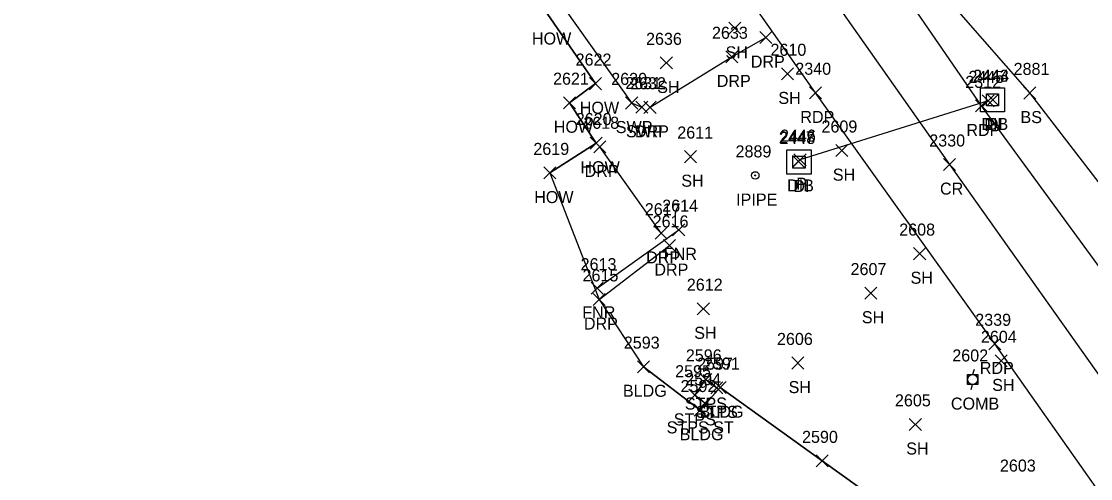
# Model space of a CAD drawing. Extents: x 1638344 to 1639591, y 610835 to 612202.
# Drawn here: x 1638879.7 to 1639057.3, y 611382.3 to 611458.3 of the extents above; entities that cross this region are included whole.
import ezdxf

# ---------------------------------------------------------------- set-up
doc = ezdxf.new("R2010")
doc.units = 0
for name, color, linetype in [('D_A', 7, 'Continuous'), ('D_I', 7, 'Continuous'), ('D_TIC', 7, 'Continuous'), ('DCP', 7, 'Continuous'), ('DS', 7, 'Continuous'), ('L_A', 7, 'Continuous'), ('L_I', 7, 'Continuous'), ('L_TIC', 7, 'Continuous'), ('LBC', 7, 'Continuous'), ('LBF', 7, 'Continuous'), ('LELB', 7, 'Continuous'), ('LFNC', 7, 'Continuous'), ('LSOGP', 7, 'Continuous'), ('M_A', 7, 'Continuous'), ('M_I', 7, 'Continuous'), ('MPIP', 7, 'Continuous'), ('P_A', 7, 'Continuous'), ('P_I', 7, 'Continuous'), ('P_TIC', 7, 'Continuous'), ('PET', 7, 'Continuous'), ('PRC', 7, 'Continuous'), ('R_A', 7, 'Continuous'), ('R_I', 7, 'Continuous'), ('R_TIC', 7, 'Continuous'), ('RDP', 7, 'Continuous'), ('RSW', 7, 'Continuous'), ('U_A', 7, 'Continuous'), ('U_I', 7, 'Continuous'), ('UP', 7, 'Continuous')]:
    doc.layers.add(name, color=color, linetype=linetype)

msp = doc.modelspace()

# ---------------------------------------------------------------- linework, layer by layer
at = {"layer": 'D_TIC'}
for points in [[(1639039.24, 611444.05), (1639041.24, 611446.05)], [(1639041.24, 611444.05), (1639039.24, 611446.05)], [(1639040.03, 611444.23), (1639042.03, 611446.23)], [(1639042.03, 611444.23), (1639040.03, 611446.23)], [(1639007.76, 611434.01), (1639009.76, 611436.01)], [(1639009.76, 611434.01), (1639007.76, 611436.01)], [(1639008.01, 611434.29), (1639010.01, 611436.29)], [(1639010.01, 611434.29), (1639008.01, 611436.29)]]:
    msp.add_lwpolyline(points, dxfattribs=at)
at = {"layer": 'DCP'}
msp.add_lwpolyline([(1639040.24, 611445.05), (1639009.01, 611435.29)], dxfattribs=at)
at = {"layer": 'DS'}
for p, q in [((1639038.97, 611447.24), (1639042.97, 611447.24)), ((1639038.97, 611443.24), (1639038.97, 611447.24)), ((1639039.97, 611444.24), (1639039.97, 611446.24)), ((1639039.97, 611446.24), (1639041.97, 611446.24)), ((1639041.97, 611446.24), (1639041.97, 611444.24)), ((1639042.97, 611447.24), (1639042.97, 611443.24)), ((1639041.97, 611444.24), (1639039.97, 611444.24)), ((1639040.98, 611445.24), (1639040.98, 611445.24)), ((1639040.98, 611445.24), (1639040.98, 611445.24)), ((1639042.97, 611443.24), (1639038.97, 611443.24)), ((1639006.85, 611436.9), (1639010.85, 611436.9)), ((1639006.85, 611432.9), (1639006.85, 611436.9)), ((1639010.85, 611436.9), (1639010.85, 611432.9)), ((1639007.85, 611433.9), (1639007.85, 611435.9)), ((1639007.85, 611435.9), (1639009.85, 611435.9)), ((1639009.85, 611435.9), (1639009.85, 611433.9)), ((1639009.85, 611433.9), (1639007.85, 611433.9)), ((1639008.85, 611434.91), (1639008.85, 611434.91)), ((1639008.85, 611434.91), (1639008.85, 611434.91)), ((1639010.85, 611432.9), (1639006.85, 611432.9))]:
    msp.add_line(p, q, dxfattribs=at)
at = {"layer": 'L_TIC'}
for points in [[(1638997.17, 611456.12), (1638999.17, 611458.12)], [(1638999.17, 611456.12), (1638997.17, 611458.12)], [(1638985.82, 611450.37), (1638987.82, 611452.37)], [(1638987.82, 611450.37), (1638985.82, 611452.37)], [(1639005.93, 611448.54), (1639007.93, 611450.54)], [(1639007.93, 611448.54), (1639005.93, 611450.54)], [(1638974.07, 611446.92), (1638976.07, 611448.92)], [(1638976.07, 611446.92), (1638974.07, 611448.92)], [(1639046.18, 611445.37), (1639048.17, 611447.37)], [(1639048.17, 611445.37), (1639046.18, 611447.37)], [(1638969.75, 611443.75), (1638971.75, 611445.75)], [(1638971.75, 611443.75), (1638969.75, 611445.75)], [(1638974.17, 611437.04), (1638976.17, 611439.04)], [(1638976.17, 611437.04), (1638974.17, 611439.04)], [(1639014.97, 611435.8), (1639016.97, 611437.8)], [(1639016.97, 611435.8), (1639014.97, 611437.8)], [(1638989.81, 611434.79), (1638991.81, 611436.79)], [(1638991.81, 611434.79), (1638989.81, 611436.79)], [(1638966.49, 611432.09), (1638968.49, 611434.09)], [(1638968.49, 611432.09), (1638966.49, 611434.09)], [(1638987.87, 611422.65), (1638989.87, 611424.65)], [(1638989.87, 611422.65), (1638987.87, 611424.65)], [(1639027.88, 611418.68), (1639029.88, 611420.68)], [(1639029.88, 611418.68), (1639027.88, 611420.68)], [(1638974.33, 611412.93), (1638976.33, 611414.93)], [(1638976.33, 611412.93), (1638974.33, 611414.93)], [(1639019.79, 611412.12), (1639021.79, 611414.12)], [(1639021.79, 611412.12), (1639019.79, 611414.12)], [(1638991.96, 611409.53), (1638993.96, 611411.53)], [(1638993.96, 611409.53), (1638991.96, 611411.53)], [(1638982.02, 611399.9), (1638984.02, 611401.9)], [(1638984.02, 611399.9), (1638982.02, 611401.9)], [(1639007.63, 611400.51), (1639009.63, 611402.51)], [(1639009.63, 611400.51), (1639007.63, 611402.51)], [(1639041.43, 611400.87), (1639043.43, 611402.87)], [(1639043.43, 611400.87), (1639041.43, 611402.87)], [(1638992.38, 611397.78), (1638994.38, 611399.78)], [(1638994.38, 611397.78), (1638992.38, 611399.78)], [(1638994.19, 611396.4), (1638996.19, 611398.4)], [(1638996.19, 611396.4), (1638994.19, 611398.4)], [(1638994.76, 611396.43), (1638996.76, 611398.43)], [(1638996.76, 611396.43), (1638994.76, 611398.43)], [(1638990.54, 611395.15), (1638992.54, 611397.15)], [(1638992.54, 611395.15), (1638990.54, 611397.15)], [(1638991.44, 611392.68), (1638993.44, 611394.68)], [(1638993.44, 611392.68), (1638991.44, 611394.68)], [(1638992.22, 611393.82), (1638994.22, 611395.82)], [(1638994.22, 611393.82), (1638992.22, 611395.82)], [(1639027.16, 611390.31), (1639029.16, 611392.31)], [(1639029.16, 611390.31), (1639027.16, 611392.31)], [(1639011.69, 611384.24), (1639013.69, 611386.24)], [(1639013.69, 611384.24), (1639011.69, 611386.24)]]:
    msp.add_lwpolyline(points, dxfattribs=at)
at = {"layer": 'LBC'}
for points in [[(1638967.49, 611433.08), (1638975.17, 611438.04), (1638970.75, 611444.76), (1638975.07, 611447.92), (1638967.12, 611459.42), (1638958.39, 611472.15), (1638953.37, 611468.84), (1638948.31, 611476.61)], [(1639030.18, 611240.11), (1639055.01, 611274.11), (1639074.76, 611301.1), (1639056.76, 611314.92), (1639059.81, 611319.01), (1639041.03, 611332.86), (1639050.69, 611345.89), (1639051.32, 611346.8), (1639056.15, 611353.65), (1639047.23, 611360.01), (1639049.34, 611363.03), (1639049.78, 611363.31), (1639052.48, 611367.11), (1639048.07, 611370.38), (1639042.99, 611363.34), (1639028.13, 611374.16), (1639012.69, 611385.24), (1638995.76, 611397.43), (1638992.44, 611393.68), (1638983.02, 611400.9)]]:
    msp.add_lwpolyline(points, dxfattribs=at)
at = {"layer": 'LBF'}
msp.add_lwpolyline([(1638993.22, 611394.82), (1638991.53, 611396.15), (1638993.38, 611398.78), (1638995.19, 611397.4)], dxfattribs=at)
at = {"layer": 'LELB'}
msp.add_lwpolyline([(1639083.1, 611392.43), (1639064.29, 611424.19), (1639047.18, 611446.37), (1639027.15, 611469.33), (1639020.17, 611481.13), (1639024.02, 611486.6)], dxfattribs=at)
at = {"layer": 'LFNC'}
msp.add_lwpolyline([(1638975.33, 611413.93), (1638988.87, 611423.65)], dxfattribs=at)
at = {"layer": 'LSOGP'}
msp.add_lwpolyline([(1638866.35, 611571.46), (1638891.21, 611537.16), (1638898.26, 611527.19), (1638908.02, 611525.06), (1638919.13, 611516.13), (1638930.92, 611504.47), (1638933.49, 611502.4), (1638935.84, 611500.51), (1638941.41, 611480.46), (1638948.31, 611476.61), (1638953.37, 611468.84), (1638958.39, 611472.15), (1638967.12, 611459.42), (1638975.07, 611447.92), (1638970.75, 611444.76), (1638975.17, 611438.04), (1638967.49, 611433.08), (1638975.65, 611412.07), (1638983.02, 611400.9), (1638992.44, 611393.68), (1638995.76, 611397.43), (1639012.69, 611385.24), (1639028.13, 611374.16)], dxfattribs=at)
at = {"layer": 'MPIP'}
for radius in [0.625, 0.0833]:
    msp.add_circle((1639001.58, 611432.67), radius, dxfattribs=at)
at = {"layer": 'P_TIC'}
for points in [[(1639010.58, 611445.4), (1639012.58, 611447.4)], [(1639012.58, 611445.4), (1639010.58, 611447.4)], [(1639038.15, 611443.22), (1639040.15, 611445.22)], [(1639040.15, 611443.22), (1639038.15, 611445.22)], [(1639032.82, 611433.48), (1639034.82, 611435.48)], [(1639034.82, 611433.48), (1639032.82, 611435.48)], [(1639040.38, 611403.69), (1639042.38, 611405.69)], [(1639042.38, 611403.69), (1639040.38, 611405.69)]]:
    msp.add_lwpolyline(points, dxfattribs=at)
at = {"layer": 'PET'}
for points in [[(1639148.64, 611331.08), (1639142.07, 611329.18), (1639135.7, 611328.74), (1639125.69, 611331.15), (1639119.18, 611334.88), (1639114.19, 611340.57), (1639098.76, 611361.78), (1639080.32, 611387.34), (1639061.62, 611413.48), (1639039.15, 611444.22), (1639014.34, 611480.36), (1638988.41, 611516.9), (1638963.39, 611551.85), (1638935.46, 611588.7), (1638918.51, 611609.36), (1638899.73, 611630.86), (1638874.41, 611653.86), (1638846.55, 611674.47), (1638833.14, 611682.54), (1638823.86, 611689.16)], [(1639117.36, 611283.38), (1639114.12, 611301.89), (1639095.51, 611328.5), (1639070.51, 611363.26), (1639041.38, 611404.69), (1639011.58, 611446.4), (1638984.33, 611485.15), (1638954.17, 611527.5), (1638934.33, 611554.77), (1638918.88, 611575.58), (1638893.27, 611605.67), (1638868.12, 611629.84), (1638836.66, 611652.85), (1638812.43, 611667.64)]]:
    msp.add_lwpolyline(points, dxfattribs=at)
at = {"layer": 'PRC'}
msp.add_lwpolyline([(1638818.79, 611678.84), (1638843.98, 611663.35), (1638876.44, 611637.39), (1638906.24, 611607.19), (1638934.14, 611573.69), (1638965.31, 611531.43), (1638998.82, 611484.34), (1639033.82, 611434.48), (1639068.01, 611386.3), (1639093.94, 611350.49), (1639111.89, 611325.38), (1639129.23, 611302.77)], dxfattribs=at)
at = {"layer": 'R_TIC'}
for points in [[(1639002.36, 611454.59), (1639004.36, 611456.59)], [(1639004.36, 611454.59), (1639002.36, 611456.59)], [(1638996.71, 611451.38), (1638998.71, 611453.38)], [(1638998.71, 611451.38), (1638996.71, 611453.38)], [(1638980.06, 611443.71), (1638982.06, 611445.71)], [(1638982.06, 611443.71), (1638980.06, 611445.71)], [(1638981.76, 611443.01), (1638983.76, 611445.01)], [(1638983.76, 611443.01), (1638981.76, 611445.01)], [(1638983.11, 611442.99), (1638985.11, 611444.99)], [(1638985.11, 611442.99), (1638983.11, 611444.99)], [(1638974.77, 611436.42), (1638976.77, 611438.42)], [(1638976.77, 611436.42), (1638974.77, 611438.42)], [(1638984.98, 611422.06), (1638986.98, 611424.06)], [(1638986.98, 611422.06), (1638984.98, 611424.06)], [(1638986.35, 611420.04), (1638988.34, 611422.04)], [(1638988.34, 611420.04), (1638986.35, 611422.04)], [(1638974.65, 611411.07), (1638976.65, 611413.07)], [(1638976.65, 611411.07), (1638974.65, 611413.07)]]:
    msp.add_lwpolyline(points, dxfattribs=at)
at = {"layer": 'RDP'}
for points in [[(1638984.11, 611443.99), (1638997.71, 611452.38), (1639003.36, 611455.59)], [(1638985.98, 611423.06), (1638975.77, 611437.42)], [(1638975.65, 611412.07), (1638987.34, 611421.04)]]:
    msp.add_lwpolyline(points, dxfattribs=at)
at = {"layer": 'RSW'}
msp.add_lwpolyline([(1638949.07, 611476.91), (1638955.12, 611480.86), (1638963.04, 611470.12), (1638981.06, 611444.71), (1638982.76, 611444.01)], dxfattribs=at)
at = {"layer": 'UP'}
for p, q in [((1639037.93, 611400.43), (1639037.68, 611399.6)), ((1639036.85, 611397.93), (1639036.85, 611399.6)), ((1639036.85, 611399.6), (1639038.52, 611399.6)), ((1639038.52, 611397.93), (1639036.85, 611397.93)), ((1639037.43, 611397.1), (1639037.68, 611397.93)), ((1639037.68, 611398.77), (1639037.68, 611398.77)), ((1639038.52, 611399.6), (1639038.52, 611397.93))]:
    msp.add_line(p, q, dxfattribs=at)
msp.add_circle((1639037.68, 611398.77), 0.833, dxfattribs=at)

# ---------------------------------------------------------------- texts
at = {"layer": 'D_A'}
for s, p in [('DIB', (1639039.13, 611440.23)), ('DI', (1639040.03, 611440.24)), ('P', (1639039.61, 611440.05)), ('DIB', (1639006.87, 611430.01)), ('DI', (1639007.91, 611429.91)), ('P', (1639008.39, 611430.29))]:
    msp.add_text(s, height=2, dxfattribs=at).set_placement(p)
at = {"layer": 'D_I'}
for s, p in [('2445', (1639036.98, 611448.05)), ('2443', (1639037.72, 611448.24)), ('2444', (1639037.77, 611448.23)), ('2447', (1639005.5, 611438.01)), ('2448', (1639005.59, 611437.91)), ('2446', (1639005.7, 611438.29))]:
    msp.add_text(s, height=2, dxfattribs=at).set_placement(p)
at = {"layer": 'L_A'}
for s, p in [('HOW', (1638964.5, 611454.42)), ('SH', (1638996.66, 611452.12)), ('SH', (1638985.31, 611446.37)), ('SH', (1639005.42, 611444.55)), ('HOW', (1638972.45, 611442.92)), ('BS', (1639045.62, 611441.37)), ('HOW', (1638968.14, 611439.76)), ('HOW', (1638972.56, 611433.04)), ('SH', (1639014.46, 611431.8)), ('SH', (1638989.3, 611430.8)), ('HOW', (1638964.88, 611428.08)), ('FNR', (1638986.4, 611418.65)), ('SH', (1639027.37, 611414.68)), ('FNR', (1638972.87, 611408.93)), ('SH', (1639019.28, 611408.12)), ('SH', (1638991.45, 611405.53)), ('BLDG', (1638979.61, 611395.9)), ('SH', (1639007.12, 611396.51)), ('SH', (1639040.92, 611396.87)), ('STPS', (1638989.9, 611393.78)), ('STPS', (1638991.71, 611392.4)), ('BLDG', (1638992.35, 611392.43)), ('STPS', (1638988.05, 611391.15)), ('STPS ST', (1638986.87, 611389.82)), ('BLDG', (1638989.03, 611388.68)), ('SH', (1639026.65, 611386.31))]:
    msp.add_text(s, height=2, dxfattribs=at).set_placement(p)
at = {"layer": 'L_I'}
for s, p in [('2636', (1638983.45, 611454.37)), ('2622', (1638971.76, 611450.92)), ('2610', (1639004.11, 611452.55)), ('2881', (1639044.48, 611449.37)), ('2621', (1638968.01, 611447.75)), ('2620', (1638971.78, 611441.04)), ('2611', (1638988.64, 611438.8)), ('2609', (1639012.58, 611439.8)), ('2619', (1638964.74, 611436.08)), ('2614', (1638986.13, 611426.65)), ('2608', (1639025.49, 611422.68)), ('2613', (1638972.59, 611416.93)), ('2607', (1639017.41, 611416.12)), ('2612', (1638990.22, 611413.53)), ('2604', (1639039.05, 611404.87)), ('2593', (1638979.76, 611403.9)), ('2606', (1639005.19, 611404.51)), ('2596', (1638990.06, 611401.78)), ('2597', (1638991.93, 611400.4)), ('2591', (1638993.07, 611400.43)), ('2595', (1638988.28, 611399.15)), ('2594', (1638989.96, 611397.82)), ('2592', (1638989.18, 611396.68)), ('2605', (1639024.78, 611394.31)), ('2590', (1639009.35, 611388.24)), ('2603', (1639042.21, 611383.47))]:
    msp.add_text(s, height=2, dxfattribs=at).set_placement(p)
at = {"layer": 'M_A'}
msp.add_text('IPIPE', height=2, dxfattribs=at).set_placement((1638998.41, 611427.67))
at = {"layer": 'M_I'}
msp.add_text('2889', height=2, dxfattribs=at).set_placement((1638998.31, 611435.67))
at = {"layer": 'P_A'}
for s, p in [('RDP', (1639009.07, 611441.4)), ('RDP', (1639036.64, 611439.22)), ('CR', (1639032.26, 611429.48)), ('RDP', (1639038.87, 611399.69))]:
    msp.add_text(s, height=2, dxfattribs=at).set_placement(p)
at = {"layer": 'P_I'}
for s, p in [('2340', (1639008.23, 611449.4)), ('2312', (1639036.46, 611447.22)), ('2330', (1639030.48, 611437.48)), ('2339', (1639038.11, 611407.69))]:
    msp.add_text(s, height=2, dxfattribs=at).set_placement(p)
at = {"layer": 'R_A'}
for s, p in [('DRP', (1639000.84, 611450.59)), ('DRP', (1638995.19, 611447.38)), ('SWP', (1638978.43, 611439.71)), ('SWP', (1638980.12, 611439.01)), ('DRP', (1638981.6, 611438.99)), ('DRP', (1638973.26, 611432.42)), ('DRP', (1638983.47, 611418.06)), ('DRP', (1638984.83, 611416.04)), ('DRP', (1638973.13, 611407.07))]:
    msp.add_text(s, height=2, dxfattribs=at).set_placement(p)
at = {"layer": 'R_I'}
for s, p in [('2633', (1638994.4, 611455.38)), ('2630', (1638977.67, 611447.71)), ('2631', (1638980.02, 611447.01)), ('2632', (1638980.8, 611446.99)), ('2618', (1638973.03, 611440.42)), ('2617', (1638983.24, 611426.06)), ('2616', (1638984.55, 611424.04)), ('2615', (1638972.91, 611415.07))]:
    msp.add_text(s, height=2, dxfattribs=at).set_placement(p)
at = {"layer": 'U_A'}
msp.add_text('COMB', height=2, dxfattribs=at).set_placement((1639034.07, 611393.77))
at = {"layer": 'U_I'}
msp.add_text('2602', height=2, dxfattribs=at).set_placement((1639034.3, 611401.77))

doc.saveas('drawing.dxf')
